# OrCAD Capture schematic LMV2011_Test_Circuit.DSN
size A; title: LMV2011 High Precision, Rail-to-Rail Output Operational; rev: 1.1; note: Datasheet: SNOSA32C EVM: N/A
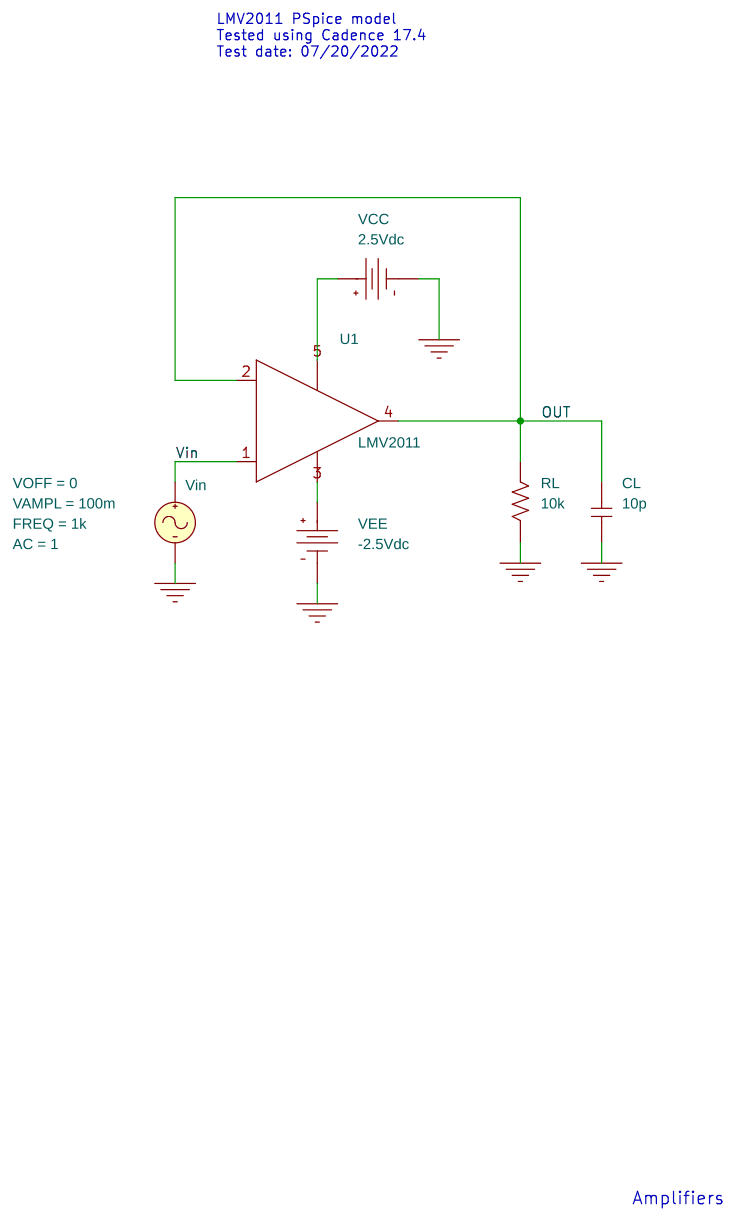
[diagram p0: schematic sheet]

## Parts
CL  10p  [RAD/CK05]
RL  10k  [AX/RC05]
U1  LMV2011
VCC  VDC
VEE  VDC
Vin  VSIN

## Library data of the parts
CL = C
RL = R
U1 = LMV2011
VCC = VDC: DC: 2.5Vdc
VEE = VDC: DC: -2.5Vdc
Vin = VSIN: AC: 1; FREQ: 1k; VAMPL: 100m; VOFF: 0

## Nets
Vin: U1.1(+) Vin.1(+)
0: CL.1 RL.1 VCC.1(-) VEE.1(-) Vin.2(-)
OUT: CL.2 RL.2 U1.2(-) U1.4(OUT)
N23017: U1.3(V-) VEE.0(+)
N37517: U1.5(V+) VCC.0(+)

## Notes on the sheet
- LMV2011 PSpice model
  Tested using Cadence 17.4
  Test date: 07/20/2022
- Amplifiers
